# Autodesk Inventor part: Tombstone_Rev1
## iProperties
Created: 2008-11
Part Number: Tombstone_Rev1
Document SubType Name: Modeling
Designer: claivier
Norme de conversion: STEP AP214IS
Nom du fichier: Tombstone_Rev1.STEP
Préprocesseur: SolidWorks 2008
Postprocesseur: Build: 344a, Release: 11 SP2 - Date: Fri 08/18/2006
Unités envoyées: INCHES
Incertitude: 1e-05
Author: claivier
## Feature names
1. Base1
